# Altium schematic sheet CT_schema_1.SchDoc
size 446 x 367 mm
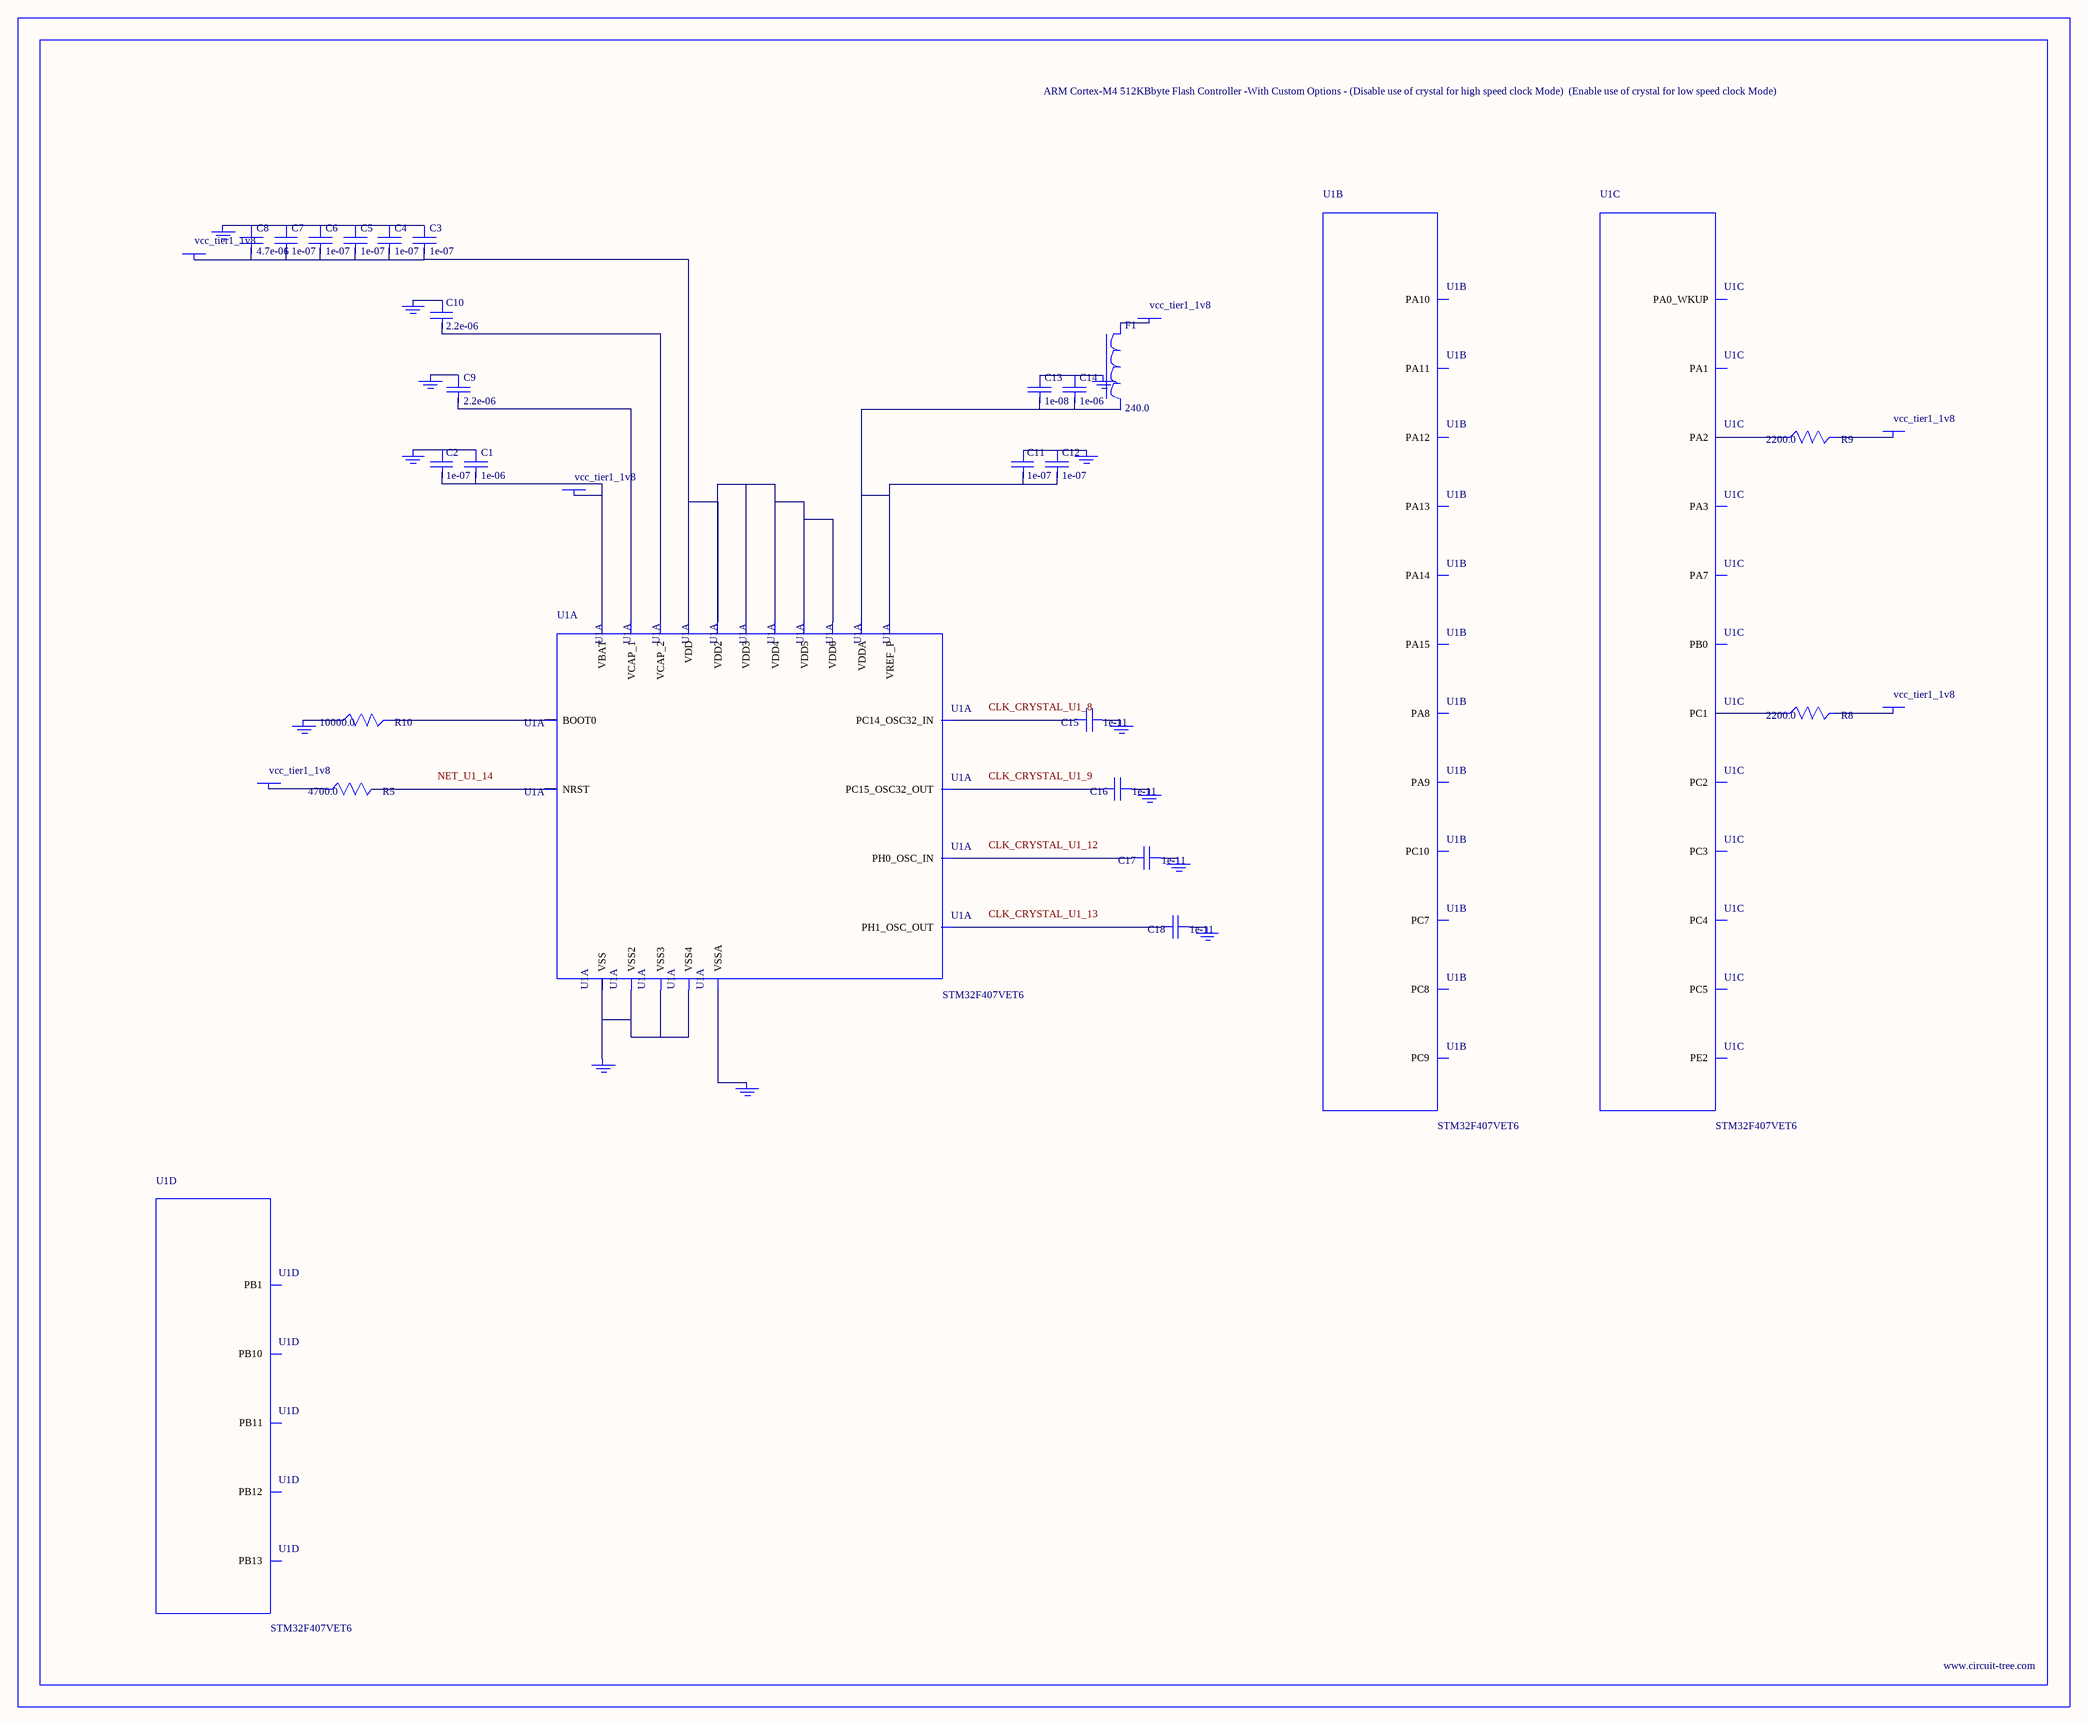
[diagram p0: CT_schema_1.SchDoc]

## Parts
BORDER0  (no value)
C1  1e-06  [C0603]
C2  1e-07  [C0603]
C3  1e-07  [C0603]
C4  1e-07  [C0603]
C5  1e-07  [C0603]
C6  1e-07  [C0603]
C7  1e-07  [C0603]
C8  4.7e-06  [C0603]
C9  2.2e-06  [C0603]
C10  2.2e-06  [C0603]
C11  1e-07  [C0603]
C12  1e-07  [C0603]
C13  1e-08  [C0603]
C14  1e-06  [C0603]
C15  1e-11  [C0402]
C16  1e-11  [C0402]
C17  1e-11  [C0402]
C18  1e-11  [C0402]
F1  240.0  [L0603]
GND_INSTANCE_0_0  (no value)
GND_INSTANCE_0_1  (no value)
GND_INSTANCE_0_2  (no value)
GND_INSTANCE_0_3  (no value)
GND_INSTANCE_0_4  (no value)
GND_INSTANCE_0_5  (no value)
GND_INSTANCE_0_6  (no value)
GND_INSTANCE_0_7  (no value)
GND_INSTANCE_0_8  (no value)
GND_INSTANCE_0_9  (no value)
GND_INSTANCE_0_10  (no value)
GND_INSTANCE_0_11  (no value)
GND_INSTANCE_0_12  (no value)
POWER_INSTANCE_0_0  vcc_tier1_1v8
POWER_INSTANCE_0_1  vcc_tier1_1v8
POWER_INSTANCE_0_2  vcc_tier1_1v8
POWER_INSTANCE_0_3  vcc_tier1_1v8
POWER_INSTANCE_0_4  vcc_tier1_1v8
POWER_INSTANCE_0_5  vcc_tier1_1v8
R5  4700.0  [R0603]
R8  2200.0  [R0603]
R9  2200.0  [R0603]
R10  10000.0  [R0603]
U1  STM32F407VET6  [LQFP100]  (parts A,B,C,D of 8)

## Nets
NetC1_1: C1.1 C2.1 GND_INSTANCE_0_0.0(GND)
NetC1_2: C1.2 C2.2 POWER_INSTANCE_0_0.0(PWR) U1.6(VBAT)
NetC3_1: C3.1 C4.1 C5.1 C6.1 C7.1 C8.1 GND_INSTANCE_0_3.0(GND)
NetC3_2: C3.2 C4.2 C5.2 C6.2 C7.2 C8.2 POWER_INSTANCE_0_1.0(PWR) U1.11(VDD) U1.19(VDD2) U1.28(VDD3) U1.50(VDD4) U1.75(VDD5) U1.100(VDD6)
NetC9_1: C9.1 GND_INSTANCE_0_9.0(GND)
NetC9_2: C9.2 U1.49(VCAP_1)
NetC10_1: C10.1 GND_INSTANCE_0_10.0(GND)
NetC10_2: C10.2 U1.73(VCAP_2)
NetC11_1: C11.1 C12.1 GND_INSTANCE_0_7.0(GND)
NetC11_2: C11.2 C12.2 C13.2 C14.2 U1.21(VREF_P) U1.22(VDDA)
NetC13_1: C13.1 C14.1 GND_INSTANCE_0_8.0(GND)
NetC15_1: C15.1 GND_INSTANCE_0_1.0(GND)
NetC15_2: C15.2 U1.8(PC14_OSC32_IN)
NetC16_1: C16.1 GND_INSTANCE_0_2.0(GND)
NetC16_2: C16.2 U1.9(PC15_OSC32_OUT)
NetC17_1: C17.1 GND_INSTANCE_0_4.0(GND)
NetC17_2: C17.2 U1.12(PH0_OSC_IN)
NetC18_1: C18.1 GND_INSTANCE_0_5.0(GND)
NetC18_2: C18.2 U1.13(PH1_OSC_OUT)
NetF1_1: F1.1 POWER_INSTANCE_0_2.0(PWR)
NetGND_INSTANCE_0_6_0: GND_INSTANCE_0_6.0(GND) U1.20(VSSA)
NetGND_INSTANCE_0_11_0: GND_INSTANCE_0_11.0(GND) R10.1
NetGND_INSTANCE_0_12_0: GND_INSTANCE_0_12.0(GND) U1.10(VSS) U1.27(VSS2) U1.74(VSS3) U1.99(VSS4)
NetPOWER_INSTANCE_0_3_0: POWER_INSTANCE_0_3.0(PWR) R5.1
NetPOWER_INSTANCE_0_4_0: POWER_INSTANCE_0_4.0(PWR) R8.2
NetPOWER_INSTANCE_0_5_0: POWER_INSTANCE_0_5.0(PWR) R9.2
NetR5_2: R5.2 U1.14(NRST)
NetR8_1: R8.1 U1.16(PC1)
NetR9_1: R9.1 U1.25(PA2)
NetR10_2: R10.2 U1.94(BOOT0)

Not connected (* = marked no-connect by the designer): F1 2; U1 1(PE2) 17(PC2) 18(PC3) 23(PA0_WKUP) 24(PA1) 26(PA3) 32(PA7) 33(PC4) 34(PC5) 35(PB0) 36(PB1) 47(PB10) 48(PB11) 51(PB12) 52(PB13) 64(PC7) 65(PC8) 66(PC9) 67(PA8) 68(PA9) 69(PA10) 70(PA11) 71(PA12) 72(PA13) 76(PA14) 77(PA15) 78(PC10)

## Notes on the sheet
- Labels drawn without touching a wire or pin: CLK_CRYSTAL_U1_8, CLK_CRYSTAL_U1_9, CLK_CRYSTAL_U1_12, CLK_CRYSTAL_U1_13, NET_U1_14

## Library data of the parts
BORDER0 = BORDER_PAGE0
C1 C14 = C0603C105K3RACTU
C2-C7 C11 C12 = 06035C104K4Z2A
C8 = GRM188R6YA475KE15D
C9 C10 = C0603C225K8RACTU
C13 = 06035C103K4Z2A
C15-C18 = C0402C100K3GACTU
F1 = Z0603C241ASMST
GND_INSTANCE_0_0-GND_INSTANCE_0_12 = GND
POWER_INSTANCE_0_0-POWER_INSTANCE_0_5 = PWR
R5 = RC0603JR-074K7L
R8 R9 = RC0603JR-072K2L
R10 = RC0603JR-0710KL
